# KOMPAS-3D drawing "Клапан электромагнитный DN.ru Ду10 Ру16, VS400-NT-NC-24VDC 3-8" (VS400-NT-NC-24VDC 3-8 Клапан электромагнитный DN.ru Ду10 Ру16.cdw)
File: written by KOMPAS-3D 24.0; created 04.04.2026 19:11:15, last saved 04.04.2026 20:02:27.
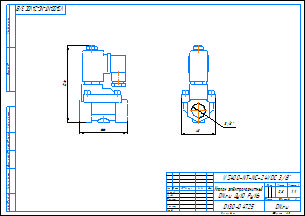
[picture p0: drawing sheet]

Document properties: c3d_UniqueCompID: ef56311e-7521-43dc-8291-0e6108b3d81d; Обозначение: VS400-ET-NC-220VAC 3-8; Наименование: Клапан электромагнитный DN.ru Ду10 Ру16; Автор: artio; Класс точности: c; Знак неуказанной шероховатости: Шероховатость не задана; Рассекать на разрезах: Да; Автор: artio; Форматы листов документа: A3; Полное имя файла: VS400-NT-NC-24VDC 3-8 Клапан электромагнитный DN.ru Ду10 Ру16.m3d; Масса: 0.797; Наименование: Клапан электромагнитный DN.ru Ду10 Ру16; Количество листов документа: 1; Примечание: D130-04725

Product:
- Body: Тело 1  | qty 1
    Масса: 1.030062
- Part/product: Клапан электромагнитный DN.ru Ду10 Ру16  | designation VS400-NT-NC-24VDC 3-8
    Масса: 0.797
    Раздел спецификации: Прочие изделия
    Примечание: D130-04725
    additional columns: ef56311e-7521-43dc-8291-0e6108b3d81d; VS400-ET-NC-220VAC 3-8; artio; c; Шероховатость не задана; Да

Views: Вид 1, Спереди, Проекционный вид 2
Referenced files in C:\Users\artio\OneDrive\Рабочий стол\Клапан электромагнитный DN.ru\VS400-ET-NC\VS400-ET-NC-24VDC\: VS400-ET-NC-24VDC 3-8 Клапан электромагнитный DN.ru Ду10 Ру16.m3d
Referenced files in C:\Users\artio\OneDrive\Рабочий стол\Клапан электромагнитный DN.ru\VS400-NT-NC\VS400-NT-NC-24VDC\: VS400-NT-NC-24VDC 3-8 Клапан электромагнитный DN.ru Ду10 Ру16.m3d, VS400-NT-NC-24VDC 3-8 Клапан электромагнитный DN.ru Ду10 Ру16.cdw
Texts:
  VS400-NT-NC-24VDC 3-8
  Клапан электромагнитный
  DN.ru Ду10 Ру16
  VS400-NT-NC-24VDC 3/8"
  VS400-NT-NC-24VDC 3/8"-
  Клапан электромагнитный DN.ru Ду10 Ру16
  VS400-NT-NC-24VDC 3-8 Клапан электромагнитный DN.ru Ду10 Ру16
Dimensions and other numbers on the sheet: 0; 3; 2; 4; 48; 3/8"; 66; 106; 1:1; 1; 0,8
